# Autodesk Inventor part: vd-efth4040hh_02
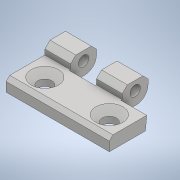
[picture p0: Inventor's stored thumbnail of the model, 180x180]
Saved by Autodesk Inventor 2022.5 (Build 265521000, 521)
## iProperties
Created: 2019-12
Part Number: vd-efth4040hh_02
Material: 一般
Document SubType Name: Modeling
Designer: ImaoCorp
Density: 1 g/cm^3
Appearance: 既定
Author: ImaoCorp
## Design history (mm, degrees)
feature "vd-efth4040hh_02"
node "ソリッド1"
